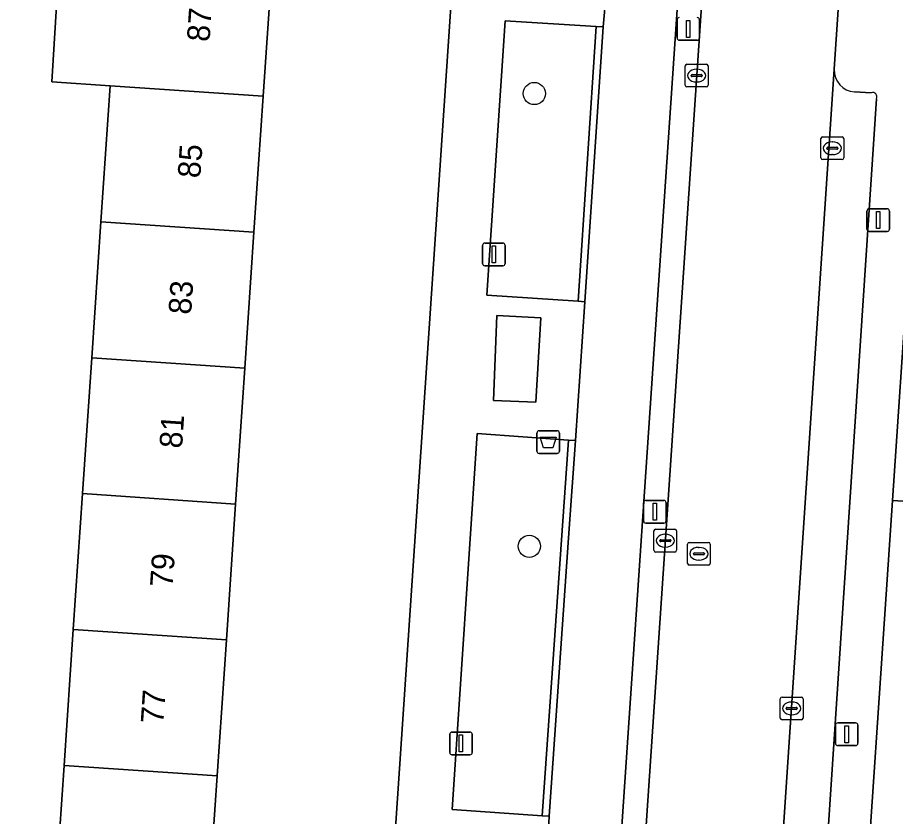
# Model space of a CAD drawing. Extents: x 161848 to 162726, y 385382 to 386521.
# Drawn here: x 162009.72 to 162048.39, y 386039.97 to 386075.17 of the extents above; entities that cross this region are included whole.
import ezdxf

# ---------------------------------------------------------------- set-up
doc = ezdxf.new("R2010")
doc.units = 0
for name, color, linetype in [('IMGEO_Afvalbak', 7, 'Continuous'), ('IMGEO_Boom', 7, 'Continuous'), ('IMGEO_Erf', 7, 'Continuous'), ('IMGEO_Fietspad_gesloten', 7, 'Continuous'), ('IMGEO_Groenvoorziening', 7, 'Continuous'), ('IMGEO_Kolk', 7, 'Continuous'), ('IMGEO_Lichtmast', 7, 'Continuous'), ('IMGEO_Pand', 7, 'Continuous'), ('IMGEO_Pand_nummerreeks', 7, 'Continuous'), ('IMGEO_Parkeervlak_open', 7, 'Continuous'), ('IMGEO_Rijbaan_lokaal_open', 7, 'Continuous'), ('IMGEO_Rioolput', 7, 'Continuous'), ('IMGEO_Verkeerseiland_open', 7, 'Continuous'), ('IMGEO_Voetpad_gesloten', 7, 'Continuous'), ('IMGEO_Voetpad_open', 7, 'Continuous')]:
    doc.layers.add(name, color=color, linetype=linetype)

msp = doc.modelspace()

# ---------------------------------------------------------------- linework, layer by layer
at = {"layer": 'IMGEO_Afvalbak'}
for p, q in [((162032.695, 386056.967), (162033.485, 386056.967)), ((162033.485, 386056.967), (162032.695, 386056.967)), ((162032.595, 386056.067), (162032.595, 386056.867)), ((162032.595, 386056.867), (162032.595, 386056.067)), ((162033.585, 386056.867), (162033.585, 386056.067)), ((162033.585, 386056.067), (162033.585, 386056.867)), ((162033.485, 386055.967), (162032.695, 386055.967)), ((162032.695, 386055.967), (162033.485, 386055.967))]:
    msp.add_line(p, q, dxfattribs=at)
msp.add_lwpolyline([(162032.738, 386056.681), (162033.442, 386056.681), (162033.293, 386056.211), (162032.887, 386056.211), (162032.738, 386056.681)], dxfattribs=at)
for centre, start, end in [((162032.695, 386056.867), 90, 180), ((162032.695, 386056.867), 90, 180), ((162033.485, 386056.867), 0, 90), ((162033.485, 386056.867), 360, 90), ((162032.695, 386056.067), 180, 270), ((162032.695, 386056.067), 180, 270), ((162033.485, 386056.067), 270, 0), ((162033.485, 386056.067), 270, 0)]:
    msp.add_arc(centre, 0.1, start, end, dxfattribs=at)
at = {"layer": 'IMGEO_Boom'}
for centre in [(162032.479, 386071.826), (162032.259, 386051.876)]:
    msp.add_circle(centre, 0.489, dxfattribs=at)
at = {"layer": 'IMGEO_Erf'}
for points in [[(162008.044, 386021.736), (162011.077, 386021.533), (162014.11, 386021.33), (162014.103, 386021.229), (162025.095, 386020.494), (162030.157, 386095.724)], [(162020.945, 386077.702), (162020.54, 386071.711), (162020.135, 386065.72), (162019.73, 386059.729), (162019.325, 386053.737), (162018.919, 386047.746), (162018.514, 386041.755), (162018.109, 386035.764), (162017.704, 386029.772), (162017.29, 386023.652), (162010.546, 386024.109), (162010.96, 386030.229), (162011.365, 386036.221), (162011.77, 386042.212), (162012.176, 386048.203), (162012.581, 386054.194), (162012.986, 386060.186), (162013.391, 386066.177), (162013.796, 386072.169), (162011.235, 386072.347), (162011.599, 386078.337)], [(162091.541, 386048.276), (162091.712, 386050.469), (162100.767, 386049.898), (162100.78, 386050.112), (162094.517, 386050.603), (162049.384, 386053.618), (162049.397, 386053.818), (162048.26, 386053.894), (162045.29, 386009.944), (162044.879, 386004.112)]]:
    msp.add_lwpolyline(points, dxfattribs=at)
at = {"layer": 'IMGEO_Fietspad_gesloten'}
msp.add_lwpolyline([(162039.139, 386128.803), (162036.98, 386096.379), (162036.936, 386095.719), (162035.651, 386076.246), (162035.507, 386074.767), (162034.711, 386062.651), (162034.288, 386056.532), (162034.007, 386052.459), (162033.132, 386039.976), (162033.055, 386038.516), (162032.013, 386022.792), (162031.948, 386021.324), (162031.937, 386021.171), (162031.287, 386012.253), (162031.231, 386011.601), (162031.196, 386011.202), (162034.41, 386011.138), (162040.007, 386093.754), (162040.137, 386095.676), (162041.2, 386111.341), (162042.155, 386125.42)], dxfattribs=at)
at = {"layer": 'IMGEO_Groenvoorziening'}
for points in [[(162055.681, 386084.218), (162050.321, 386084.573), (162048.26, 386053.894), (162049.397, 386053.818), (162049.411, 386054.017), (162050.666, 386071.553), (162054.787, 386071.274)], [(162035.208, 386074.786), (162031.204, 386075.033), (162030.384, 386062.943), (162034.412, 386062.671)], [(162032.833, 386039.997), (162033.993, 386056.554), (162029.97, 386056.852), (162028.861, 386040.269)]]:
    msp.add_lwpolyline(points, close=True, dxfattribs=at)
at = {"layer": 'IMGEO_Kolk'}
for p, q in [((162039.13, 386072.19), (162039.13, 386073.042)), ((162039.205, 386073.116), (162040.057, 386073.116)), ((162039.618, 386072.896), (162039.643, 386072.896)), ((162040.131, 386073.042), (162040.131, 386072.19)), ((162039.389, 386072.61), (162039.389, 386072.622)), ((162039.827, 386072.573), (162039.429, 386072.573)), ((162039.432, 386072.659), (162039.83, 386072.659)), ((162039.873, 386072.622), (162039.873, 386072.61)), ((162040.057, 386072.116), (162039.205, 386072.116)), ((162039.641, 386072.336), (162039.616, 386072.336)), ((162045.105, 386068.989), (162045.105, 386069.841)), ((162045.18, 386069.915), (162046.032, 386069.915)), ((162045.593, 386069.695), (162045.618, 386069.695)), ((162046.106, 386069.841), (162046.106, 386068.989)), ((162045.364, 386069.409), (162045.364, 386069.421)), ((162045.802, 386069.372), (162045.404, 386069.372)), ((162045.407, 386069.458), (162045.805, 386069.458)), ((162045.848, 386069.421), (162045.848, 386069.409)), ((162046.032, 386068.915), (162045.18, 386068.915)), ((162045.616, 386069.135), (162045.591, 386069.135)), ((162037.748, 386051.697), (162037.748, 386052.549)), ((162037.823, 386052.623), (162038.675, 386052.623)), ((162038.236, 386052.403), (162038.261, 386052.403)), ((162038.749, 386052.549), (162038.749, 386051.697)), ((162038.007, 386052.117), (162038.007, 386052.129)), ((162038.445, 386052.08), (162038.047, 386052.08)), ((162038.05, 386052.166), (162038.448, 386052.166)), ((162038.491, 386052.129), (162038.491, 386052.117)), ((162038.675, 386051.623), (162037.823, 386051.623)), ((162038.259, 386051.843), (162038.234, 386051.843)), ((162043.315, 386044.305), (162043.315, 386045.157)), ((162043.39, 386045.231), (162044.242, 386045.231)), ((162043.803, 386045.011), (162043.828, 386045.011)), ((162044.316, 386045.157), (162044.316, 386044.305)), ((162043.574, 386044.725), (162043.574, 386044.737)), ((162044.012, 386044.688), (162043.614, 386044.688)), ((162043.617, 386044.774), (162044.015, 386044.774)), ((162044.058, 386044.737), (162044.058, 386044.725)), ((162044.242, 386044.231), (162043.39, 386044.231)), ((162043.826, 386044.451), (162043.801, 386044.451))]:
    msp.add_line(p, q, dxfattribs=at)
for points in [[(162039.13, 386072.19), (162039.13, 386073.042)], [(162039.205, 386073.116), (162040.057, 386073.116)], [(162040.131, 386073.042), (162040.131, 386072.19)], [(162040.057, 386072.116), (162039.205, 386072.116)], [(162045.105, 386068.989), (162045.105, 386069.841)], [(162045.18, 386069.915), (162046.032, 386069.915)], [(162046.106, 386069.841), (162046.106, 386068.989)], [(162046.032, 386068.915), (162045.18, 386068.915)], [(162037.748, 386051.697), (162037.748, 386052.549)], [(162037.823, 386052.623), (162038.675, 386052.623)], [(162038.749, 386052.549), (162038.749, 386051.697)], [(162038.675, 386051.623), (162037.823, 386051.623)], [(162043.315, 386044.305), (162043.315, 386045.157)], [(162043.39, 386045.231), (162044.242, 386045.231)], [(162044.316, 386045.157), (162044.316, 386044.305)], [(162044.242, 386044.231), (162043.39, 386044.231)]]:
    msp.add_lwpolyline(points, dxfattribs=at)
for centre, radius, start, end in [((162039.207, 386073.04), 0.0765, 91.552, 178.448), ((162039.207, 386073.04), 0.0765, 91.552, 178.448), ((162040.055, 386073.04), 0.0765, 1.552, 88.448), ((162040.055, 386073.04), 0.0765, 1.552, 88.448), ((162039.429, 386072.619), 0.0403, 85.8775, 175.7526), ((162039.426, 386072.609), 0.0366, 178.938, 274.7102), ((162039.83, 386072.616), 0.043, 264.8664, 352.4533), ((162039.834, 386072.621), 0.0386, 1.7309, 96.639), ((162039.207, 386072.192), 0.0765, 181.552, 268.448), ((162039.207, 386072.192), 0.0765, 181.552, 268.448), ((162040.055, 386072.192), 0.0765, 271.552, 358.448), ((162040.055, 386072.192), 0.0765, 271.552, 358.448), ((162045.182, 386069.839), 0.0765, 91.552, 178.448), ((162045.182, 386069.839), 0.0765, 91.552, 178.448), ((162046.03, 386069.839), 0.0765, 1.552, 88.448), ((162046.03, 386069.839), 0.0765, 1.552, 88.448), ((162045.404, 386069.418), 0.0403, 85.8775, 175.7526), ((162045.401, 386069.408), 0.0366, 178.938, 274.7102), ((162045.805, 386069.415), 0.043, 264.8664, 352.4533), ((162045.809, 386069.42), 0.0386, 1.7309, 96.639), ((162045.182, 386068.991), 0.0765, 181.552, 268.448), ((162045.182, 386068.991), 0.0765, 181.552, 268.448), ((162046.03, 386068.991), 0.0765, 271.552, 358.448), ((162046.03, 386068.991), 0.0765, 271.552, 358.448), ((162037.825, 386052.547), 0.0765, 91.552, 178.448), ((162037.825, 386052.547), 0.0765, 91.552, 178.448), ((162038.673, 386052.547), 0.0765, 1.552, 88.448), ((162038.673, 386052.547), 0.0765, 1.552, 88.448), ((162038.047, 386052.126), 0.0403, 85.8775, 175.7526), ((162038.044, 386052.116), 0.0366, 178.938, 274.7102), ((162038.448, 386052.123), 0.043, 264.8664, 352.4533), ((162038.452, 386052.128), 0.0386, 1.7309, 96.639), ((162037.825, 386051.699), 0.0765, 181.552, 268.448), ((162037.825, 386051.699), 0.0765, 181.552, 268.448), ((162038.673, 386051.699), 0.0765, 271.552, 358.448), ((162038.673, 386051.699), 0.0765, 271.552, 358.448), ((162043.392, 386045.155), 0.0765, 91.552, 178.448), ((162043.392, 386045.155), 0.0765, 91.552, 178.448), ((162044.24, 386045.155), 0.0765, 1.552, 88.448), ((162044.24, 386045.155), 0.0765, 1.552, 88.448), ((162043.614, 386044.734), 0.0403, 85.8775, 175.7526), ((162043.611, 386044.724), 0.0366, 178.938, 274.7102), ((162044.015, 386044.731), 0.043, 264.8664, 352.4533), ((162044.019, 386044.736), 0.0386, 1.7309, 96.639), ((162043.392, 386044.307), 0.0765, 181.552, 268.448), ((162043.392, 386044.307), 0.0765, 181.552, 268.448), ((162044.24, 386044.307), 0.0765, 271.552, 358.448), ((162044.24, 386044.307), 0.0765, 271.552, 358.448)]:
    msp.add_arc(centre, radius, start, end, dxfattribs=at)
for centre, major_axis, ratio, start_param, end_param in [((162039.617, 386072.616), (-0.387, 0.002), 0.722429, 4.712389, 7.853982), ((162039.642, 386072.616), (-0.39, 0.002), 0.717154, 1.570796, 4.712389), ((162045.592, 386069.415), (-0.387, 0.002), 0.722429, 4.712389, 7.853982), ((162045.617, 386069.415), (-0.39, 0.002), 0.717154, 1.570796, 4.712389), ((162038.235, 386052.123), (-0.387, 0.002), 0.722429, 4.712389, 7.853982), ((162038.26, 386052.123), (-0.39, 0.002), 0.717154, 1.570796, 4.712389), ((162043.802, 386044.731), (-0.387, 0.002), 0.722429, 4.712389, 7.853982), ((162043.827, 386044.731), (-0.39, 0.002), 0.717154, 1.570796, 4.712389)]:
    msp.add_ellipse(centre, major_axis=major_axis, ratio=ratio, start_param=start_param, end_param=end_param, dxfattribs=at)
at = {"layer": 'IMGEO_Lichtmast'}
for p, q in [((162038.766, 386074.275), (162038.766, 386075.075)), ((162038.766, 386075.075), (162038.766, 386074.275)), ((162039.756, 386075.075), (162039.756, 386074.275)), ((162039.756, 386074.275), (162039.756, 386075.075)), ((162039.656, 386074.175), (162038.866, 386074.175)), ((162038.866, 386074.175), (162039.656, 386074.175)), ((162047.132, 386065.849), (162047.132, 386066.649)), ((162047.132, 386066.649), (162047.132, 386065.849)), ((162047.232, 386066.749), (162048.022, 386066.749)), ((162048.022, 386066.749), (162047.232, 386066.749)), ((162048.122, 386066.649), (162048.122, 386065.849)), ((162048.122, 386065.849), (162048.122, 386066.649)), ((162048.022, 386065.749), (162047.232, 386065.749)), ((162047.232, 386065.749), (162048.022, 386065.749)), ((162030.203, 386064.335), (162030.203, 386065.135)), ((162030.203, 386065.135), (162030.203, 386064.335)), ((162030.303, 386065.235), (162031.093, 386065.235)), ((162031.093, 386065.235), (162030.303, 386065.235)), ((162031.193, 386065.135), (162031.193, 386064.335)), ((162031.193, 386064.335), (162031.193, 386065.135)), ((162031.093, 386064.235), (162030.303, 386064.235)), ((162030.303, 386064.235), (162031.093, 386064.235)), ((162037.293, 386052.995), (162037.293, 386053.795)), ((162037.293, 386053.795), (162037.293, 386052.995)), ((162037.393, 386053.895), (162038.183, 386053.895)), ((162038.183, 386053.895), (162037.393, 386053.895)), ((162038.283, 386053.795), (162038.283, 386052.995)), ((162038.283, 386052.995), (162038.283, 386053.795)), ((162038.183, 386052.895), (162037.393, 386052.895)), ((162037.393, 386052.895), (162038.183, 386052.895)), ((162045.742, 386043.193), (162045.742, 386043.993)), ((162045.742, 386043.993), (162045.742, 386043.193)), ((162045.842, 386044.093), (162046.632, 386044.093)), ((162046.632, 386044.093), (162045.842, 386044.093)), ((162046.732, 386043.993), (162046.732, 386043.193)), ((162046.732, 386043.193), (162046.732, 386043.993)), ((162028.755, 386042.79), (162028.755, 386043.59)), ((162028.755, 386043.59), (162028.755, 386042.79)), ((162028.855, 386043.69), (162029.645, 386043.69)), ((162029.645, 386043.69), (162028.855, 386043.69)), ((162029.745, 386043.59), (162029.745, 386042.79)), ((162029.745, 386042.79), (162029.745, 386043.59)), ((162046.632, 386043.093), (162045.842, 386043.093)), ((162045.842, 386043.093), (162046.632, 386043.093)), ((162029.645, 386042.69), (162028.855, 386042.69)), ((162028.855, 386042.69), (162029.645, 386042.69))]:
    msp.add_line(p, q, dxfattribs=at)
for points in [[(162039.186, 386075.05), (162039.336, 386075.05), (162039.336, 386074.3), (162039.186, 386074.3), (162039.186, 386075.05)], [(162047.552, 386066.624), (162047.702, 386066.624), (162047.702, 386065.874), (162047.552, 386065.874), (162047.552, 386066.624)], [(162030.623, 386065.11), (162030.773, 386065.11), (162030.773, 386064.36), (162030.623, 386064.36), (162030.623, 386065.11)], [(162037.713, 386053.77), (162037.863, 386053.77), (162037.863, 386053.02), (162037.713, 386053.02), (162037.713, 386053.77)], [(162046.162, 386043.968), (162046.312, 386043.968), (162046.312, 386043.218), (162046.162, 386043.218), (162046.162, 386043.968)], [(162029.175, 386043.565), (162029.325, 386043.565), (162029.325, 386042.815), (162029.175, 386042.815), (162029.175, 386043.565)]]:
    msp.add_lwpolyline(points, dxfattribs=at)
for centre, start, end in [((162038.866, 386075.075), 90, 180), ((162038.866, 386075.075), 90, 180), ((162039.656, 386075.075), 0, 90), ((162039.656, 386075.075), 360, 90), ((162038.866, 386074.275), 180, 270), ((162038.866, 386074.275), 180, 270), ((162039.656, 386074.275), 270, 0), ((162039.656, 386074.275), 270, 0), ((162047.232, 386066.649), 90, 180), ((162047.232, 386066.649), 90, 180), ((162048.022, 386066.649), 0, 90), ((162048.022, 386066.649), 360, 90), ((162047.232, 386065.849), 180, 270), ((162047.232, 386065.849), 180, 270), ((162048.022, 386065.849), 270, 0), ((162048.022, 386065.849), 270, 0), ((162030.303, 386065.135), 90, 180), ((162030.303, 386065.135), 90, 180), ((162031.093, 386065.135), 0, 90), ((162031.093, 386065.135), 360, 90), ((162030.303, 386064.335), 180, 270), ((162030.303, 386064.335), 180, 270), ((162031.093, 386064.335), 270, 0), ((162031.093, 386064.335), 270, 0), ((162037.393, 386053.795), 90, 180), ((162037.393, 386053.795), 90, 180), ((162038.183, 386053.795), 0, 90), ((162038.183, 386053.795), 360, 90), ((162037.393, 386052.995), 180, 270), ((162037.393, 386052.995), 180, 270), ((162038.183, 386052.995), 270, 0), ((162038.183, 386052.995), 270, 0), ((162045.842, 386043.993), 90, 180), ((162045.842, 386043.993), 90, 180), ((162046.632, 386043.993), 0, 90), ((162046.632, 386043.993), 360, 90), ((162028.855, 386043.59), 90, 180), ((162028.855, 386043.59), 90, 180), ((162029.645, 386043.59), 0, 90), ((162029.645, 386043.59), 360, 90), ((162045.842, 386043.193), 180, 270), ((162045.842, 386043.193), 180, 270), ((162046.632, 386043.193), 270, 0), ((162046.632, 386043.193), 270, 0), ((162028.855, 386042.79), 180, 270), ((162028.855, 386042.79), 180, 270), ((162029.645, 386042.79), 270, 0), ((162029.645, 386042.79), 270, 0)]:
    msp.add_arc(centre, 0.1, start, end, dxfattribs=at)
at = {"layer": 'IMGEO_Pand'}
for points in [[(162020.945, 386077.702), (162014.202, 386078.16), (162011.599, 386078.337), (162011.235, 386072.347), (162013.796, 386072.169), (162020.54, 386071.711)], [(162020.54, 386071.711), (162013.796, 386072.169), (162013.391, 386066.177), (162020.135, 386065.72)], [(162020.135, 386065.72), (162013.391, 386066.177), (162012.986, 386060.186), (162019.73, 386059.729)], [(162019.73, 386059.729), (162012.986, 386060.186), (162012.581, 386054.194), (162019.325, 386053.737)], [(162019.325, 386053.737), (162012.581, 386054.194), (162012.176, 386048.203), (162018.919, 386047.746)], [(162018.919, 386047.746), (162012.176, 386048.203), (162011.77, 386042.212), (162018.514, 386041.755)], [(162018.514, 386041.755), (162011.77, 386042.212), (162011.365, 386036.221), (162018.109, 386035.764)]]:
    msp.add_lwpolyline(points, close=True, dxfattribs=at)
at = {"layer": 'IMGEO_Parkeervlak_open'}
for points in [[(162045.689, 386072.893), (162041.12, 386004.571)], [(162043.178, 386005.527), (162043.426, 386009.166), (162047.545, 386071.599)], [(162047.317, 386071.862), (162046.579, 386071.894)]]:
    msp.add_lwpolyline(points, dxfattribs=at)
for centre, radius, start, end in [((162046.665, 386072.866), 0.976, 178.441, 264.9541), ((162047.38, 386071.686), 0.187, 332.2999, 109.5455)]:
    msp.add_arc(centre, radius, start, end, dxfattribs=at)
at = {"layer": 'IMGEO_Rijbaan_lokaal_open'}
msp.add_lwpolyline([(162041.102, 386004.154), (162041.12, 386004.571), (162045.689, 386072.893), (162046.97, 386091.978), (162040.968, 386092.437), (162035.482, 386011.093), (162034.343, 385994.018), (162033.471, 385981.124), (162032.304, 385964.271), (162028.465, 385906.543), (162026.839, 385883.258), (162032.937, 385882.841), (162035.569, 385921.295)], dxfattribs=at)
at = {"layer": 'IMGEO_Rioolput'}
for p, q in [((162039.229, 386051.118), (162039.229, 386051.97)), ((162039.304, 386052.044), (162040.156, 386052.044)), ((162040.23, 386051.97), (162040.23, 386051.118)), ((162039.488, 386051.538), (162039.488, 386051.55)), ((162039.926, 386051.501), (162039.528, 386051.501)), ((162039.531, 386051.587), (162039.929, 386051.587)), ((162039.717, 386051.824), (162039.742, 386051.824)), ((162039.972, 386051.55), (162039.972, 386051.538)), ((162039.74, 386051.264), (162039.715, 386051.264)), ((162040.156, 386051.044), (162039.304, 386051.044))]:
    msp.add_line(p, q, dxfattribs=at)
for points in [[(162039.229, 386051.118), (162039.229, 386051.97)], [(162039.304, 386052.044), (162040.156, 386052.044)], [(162040.23, 386051.97), (162040.23, 386051.118)], [(162040.156, 386051.044), (162039.304, 386051.044)]]:
    msp.add_lwpolyline(points, dxfattribs=at)
for centre, radius, start, end in [((162039.306, 386051.968), 0.0765, 91.552, 178.448), ((162039.306, 386051.968), 0.0765, 91.552, 178.448), ((162040.154, 386051.968), 0.0765, 1.552, 88.448), ((162040.154, 386051.968), 0.0765, 1.552, 88.448), ((162039.528, 386051.547), 0.0403, 85.8775, 175.7526), ((162039.525, 386051.537), 0.0366, 178.938, 274.7102), ((162039.929, 386051.544), 0.043, 264.8664, 352.4533), ((162039.933, 386051.549), 0.0386, 1.7309, 96.639), ((162039.306, 386051.12), 0.0765, 181.552, 268.448), ((162039.306, 386051.12), 0.0765, 181.552, 268.448), ((162040.154, 386051.12), 0.0765, 271.552, 358.448), ((162040.154, 386051.12), 0.0765, 271.552, 358.448)]:
    msp.add_arc(centre, radius, start, end, dxfattribs=at)
for centre, major_axis, ratio, start_param, end_param in [((162039.716, 386051.544), (-0.387, 0.002), 0.722429, 4.712389, 7.853982), ((162039.741, 386051.544), (-0.39, 0.002), 0.717154, 1.570796, 4.712389)]:
    msp.add_ellipse(centre, major_axis=major_axis, ratio=ratio, start_param=start_param, end_param=end_param, dxfattribs=at)
at = {"layer": 'IMGEO_Verkeerseiland_open'}
for points in [[(162035.482, 386011.093), (162040.968, 386092.437), (162041.054, 386093.689), (162040.007, 386093.754), (162034.41, 386011.138)], [(162035.208, 386074.786), (162034.412, 386062.671), (162034.711, 386062.651), (162035.507, 386074.767)], [(162032.833, 386039.997), (162033.132, 386039.976), (162034.007, 386052.459), (162034.288, 386056.532), (162033.993, 386056.554)]]:
    msp.add_lwpolyline(points, close=True, dxfattribs=at)
at = {"layer": 'IMGEO_Voetpad_gesloten'}
msp.add_lwpolyline([(162032.763, 386061.938), (162030.834, 386062.048), (162030.689, 386058.299), (162032.553, 386058.226)], close=True, dxfattribs=at)
at = {"layer": 'IMGEO_Voetpad_open'}
for points in [[(162048.498, 386113.868), (162048.375, 386112.1), (162046.97, 386091.978), (162045.689, 386072.893)], [(162030.157, 386095.724), (162025.095, 386020.494), (162024.567, 386012.654)], [(162044.521, 385999.036), (162044.879, 386004.112), (162045.29, 386009.944), (162048.26, 386053.894), (162050.321, 386084.573)], [(162026.839, 386011.243), (162027.596, 386021.487), (162031.673, 386021.19), (162031.937, 386021.171), (162031.948, 386021.324), (162032.013, 386022.792), (162031.714, 386022.812), (162027.689, 386023.077), (162028.778, 386038.763), (162032.755, 386038.533), (162033.055, 386038.516), (162033.132, 386039.976), (162032.833, 386039.997), (162028.861, 386040.269), (162029.97, 386056.852), (162033.993, 386056.554), (162034.288, 386056.532), (162034.711, 386062.651), (162034.412, 386062.671), (162030.384, 386062.943), (162031.204, 386075.033), (162035.208, 386074.786), (162035.507, 386074.767), (162035.651, 386076.246)], [(162047.545, 386071.599), (162043.426, 386009.166), (162043.178, 386005.527)], [(162046.579, 386071.894), (162047.317, 386071.862)]]:
    msp.add_lwpolyline(points, dxfattribs=at)
msp.add_lwpolyline([(162032.763, 386061.938), (162032.553, 386058.226), (162030.689, 386058.299), (162030.834, 386062.048)], close=True, dxfattribs=at)
for centre, radius, start, end in [((162046.665, 386072.866), 0.976, 178.441, 264.9541), ((162047.38, 386071.686), 0.187, 332.2999, 109.5455)]:
    msp.add_arc(centre, radius, start, end, dxfattribs=at)

# ---------------------------------------------------------------- texts
at = {"layer": 'IMGEO_Pand_nummerreeks'}
for s, rotation, p in [('87', 86.1327, (162018.175, 386074.088)), ('85', 86.131, (162017.768, 386068.078)), ('83', 86.131, (162017.362, 386062.067)), ('81', 86.131, (162016.963, 386056.169)), ('79', 86.131, (162016.549, 386050.046)), ('77', 86.131, (162016.142, 386044.035))]:
    msp.add_text(s, height=1, rotation=rotation, dxfattribs=at).set_placement(p)

doc.saveas('drawing.dxf')
